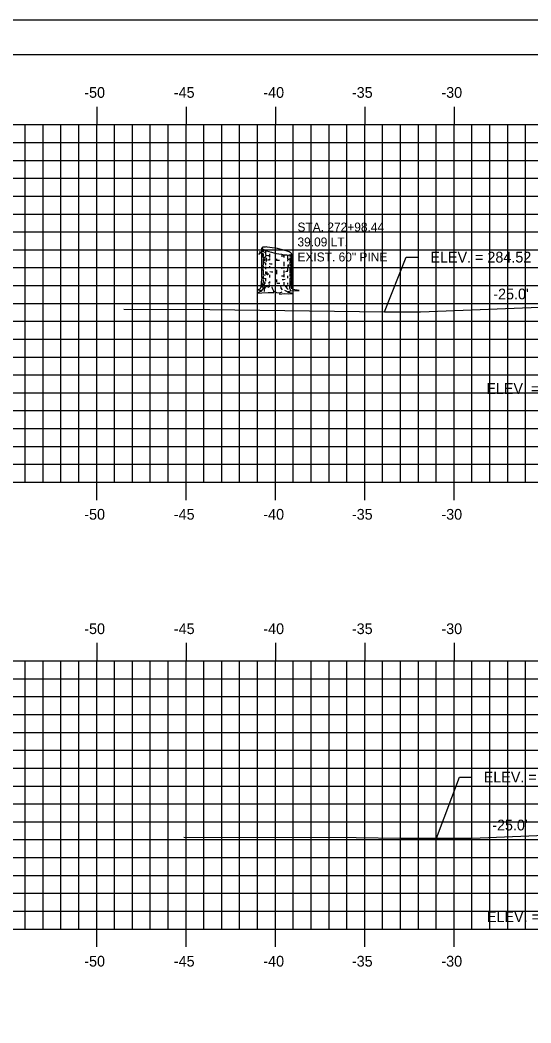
# Model space of a CAD drawing. Extents: x 852672 to 852842, y 366268 to 366378.
# Drawn here: x 852700.8 to 852729.4, y 366322.1 to 366378.2 of the extents above; entities that cross this region are included whole.
import ezdxf

# ---------------------------------------------------------------- set-up
doc = ezdxf.new("R2010")
doc.units = 0
for name, color, linetype in [('BORDER', 7, 'Continuous'), ('D_Text_Monospaced', 7, 'Continuous'), ('D_Text_Standard', 7, 'Continuous'), ('H_V ANNOTATION', 7, 'Continuous'), ('MAJOR', 7, 'Continuous'), ('MINOR', 7, 'Continuous'), ('PLOT BOUNDARY', 7, 'Continuous'), ('S_Roadway_Centerline', 7, 'Continuous'), ('S_Trees_Conifer_Pay', 7, 'Continuous')]:
    doc.layers.add(name, color=color, linetype=linetype)

msp = doc.modelspace()

# ---------------------------------------------------------------- linework, layer by layer
at = {"layer": 'BORDER'}
msp.add_line((852840.097, 366376.236), (852680.097, 366376.236), dxfattribs=at)
at = {"layer": 'D_Text_Standard'}
for points in [[(852721.194, 366361.85), (852722.411, 366364.913), (852723.091, 366364.913)], [(852724.103, 366332.417), (852725.395, 366335.829), (852726.075, 366335.829)]]:
    msp.add_lwpolyline(points, dxfattribs=at)
at = {"layer": 'MAJOR'}
for p, q in [((852705.096, 366373.329), (852705.096, 366372.327)), ((852710.096, 366373.329), (852710.096, 366372.327)), ((852715.096, 366373.329), (852715.096, 366372.327)), ((852720.096, 366373.329), (852720.096, 366372.327)), ((852725.096, 366373.329), (852725.096, 366372.327)), ((852685.096, 366372.327), (852825.096, 366372.327)), ((852685.096, 366372.327), (852825.096, 366372.327)), ((852705.096, 366352.327), (852705.096, 366372.327)), ((852710.096, 366352.327), (852710.096, 366372.327)), ((852715.096, 366352.327), (852715.096, 366372.327)), ((852720.096, 366352.327), (852720.096, 366372.327)), ((852725.096, 366352.327), (852725.096, 366372.327)), ((852685.096, 366367.327), (852825.096, 366367.327)), ((852685.096, 366362.327), (852825.096, 366362.327)), ((852685.096, 366357.327), (852825.096, 366357.327)), ((852685.096, 366352.327), (852825.096, 366352.327)), ((852685.096, 366352.327), (852825.096, 366352.327)), ((852705.096, 366351.325), (852705.096, 366352.327)), ((852710.096, 366351.325), (852710.096, 366352.327)), ((852715.096, 366351.325), (852715.096, 366352.327)), ((852720.096, 366351.325), (852720.096, 366352.327)), ((852725.096, 366351.325), (852725.096, 366352.327)), ((852705.096, 366343.329), (852705.096, 366342.327)), ((852710.096, 366343.329), (852710.096, 366342.327)), ((852715.096, 366343.329), (852715.096, 366342.327)), ((852720.096, 366343.329), (852720.096, 366342.327)), ((852725.096, 366343.329), (852725.096, 366342.327)), ((852685.096, 366342.327), (852825.096, 366342.327)), ((852685.096, 366342.327), (852825.096, 366342.327)), ((852705.096, 366327.327), (852705.096, 366342.327)), ((852710.096, 366327.327), (852710.096, 366342.327)), ((852715.096, 366327.327), (852715.096, 366342.327)), ((852720.096, 366327.327), (852720.096, 366342.327)), ((852725.096, 366327.327), (852725.096, 366342.327)), ((852685.096, 366337.327), (852825.096, 366337.327)), ((852685.096, 366332.327), (852825.096, 366332.327)), ((852685.096, 366327.327), (852825.096, 366327.327)), ((852685.096, 366327.327), (852825.096, 366327.327)), ((852705.096, 366326.325), (852705.096, 366327.327)), ((852710.096, 366326.325), (852710.096, 366327.327)), ((852715.096, 366326.325), (852715.096, 366327.327)), ((852720.096, 366326.325), (852720.096, 366327.327)), ((852725.096, 366326.325), (852725.096, 366327.327))]:
    msp.add_line(p, q, dxfattribs=at)
at = {"layer": 'MINOR'}
for p, q in [((852701.096, 366352.327), (852701.096, 366372.327)), ((852702.096, 366352.327), (852702.096, 366372.327)), ((852703.096, 366352.327), (852703.096, 366372.327)), ((852704.096, 366352.327), (852704.096, 366372.327)), ((852706.096, 366352.327), (852706.096, 366372.327)), ((852707.096, 366352.327), (852707.096, 366372.327)), ((852708.096, 366352.327), (852708.096, 366372.327)), ((852709.096, 366352.327), (852709.096, 366372.327)), ((852711.096, 366352.327), (852711.096, 366372.327)), ((852712.096, 366352.327), (852712.096, 366372.327)), ((852713.096, 366352.327), (852713.096, 366372.327)), ((852714.096, 366352.327), (852714.096, 366372.327)), ((852716.096, 366352.327), (852716.096, 366372.327)), ((852717.096, 366352.327), (852717.096, 366372.327)), ((852718.096, 366352.327), (852718.096, 366372.327)), ((852719.096, 366352.327), (852719.096, 366372.327)), ((852721.096, 366352.327), (852721.096, 366372.327)), ((852722.096, 366352.327), (852722.096, 366372.327)), ((852723.096, 366352.327), (852723.096, 366372.327)), ((852724.096, 366352.327), (852724.096, 366372.327)), ((852726.096, 366352.327), (852726.096, 366372.327)), ((852727.096, 366352.327), (852727.096, 366372.327)), ((852728.096, 366352.327), (852728.096, 366372.327)), ((852729.096, 366352.327), (852729.096, 366372.327)), ((852685.096, 366371.327), (852825.096, 366371.327)), ((852685.096, 366370.327), (852825.096, 366370.327)), ((852685.096, 366369.327), (852825.096, 366369.327)), ((852685.096, 366368.327), (852825.096, 366368.327)), ((852685.096, 366366.327), (852825.096, 366366.327)), ((852685.096, 366365.327), (852825.096, 366365.327)), ((852685.096, 366364.327), (852825.096, 366364.327)), ((852685.096, 366363.327), (852825.096, 366363.327)), ((852685.096, 366361.327), (852825.096, 366361.327)), ((852685.096, 366360.327), (852825.096, 366360.327)), ((852685.096, 366359.327), (852825.096, 366359.327)), ((852685.096, 366358.327), (852825.096, 366358.327)), ((852685.096, 366356.327), (852825.096, 366356.327)), ((852685.096, 366355.327), (852825.096, 366355.327)), ((852685.096, 366354.327), (852825.096, 366354.327)), ((852685.096, 366353.327), (852825.096, 366353.327)), ((852701.096, 366327.327), (852701.096, 366342.327)), ((852702.096, 366327.327), (852702.096, 366342.327)), ((852703.096, 366327.327), (852703.096, 366342.327)), ((852704.096, 366327.327), (852704.096, 366342.327)), ((852706.096, 366327.327), (852706.096, 366342.327)), ((852707.096, 366327.327), (852707.096, 366342.327)), ((852708.096, 366327.327), (852708.096, 366342.327)), ((852709.096, 366327.327), (852709.096, 366342.327)), ((852711.096, 366327.327), (852711.096, 366342.327)), ((852712.096, 366327.327), (852712.096, 366342.327)), ((852713.096, 366327.327), (852713.096, 366342.327)), ((852714.096, 366327.327), (852714.096, 366342.327)), ((852716.096, 366327.327), (852716.096, 366342.327)), ((852717.096, 366327.327), (852717.096, 366342.327)), ((852718.096, 366327.327), (852718.096, 366342.327)), ((852719.096, 366327.327), (852719.096, 366342.327)), ((852721.096, 366327.327), (852721.096, 366342.327)), ((852722.096, 366327.327), (852722.096, 366342.327)), ((852723.096, 366327.327), (852723.096, 366342.327)), ((852724.096, 366327.327), (852724.096, 366342.327)), ((852726.096, 366327.327), (852726.096, 366342.327)), ((852727.096, 366327.327), (852727.096, 366342.327)), ((852728.096, 366327.327), (852728.096, 366342.327)), ((852729.096, 366327.327), (852729.096, 366342.327)), ((852685.096, 366341.327), (852825.096, 366341.327)), ((852685.096, 366340.327), (852825.096, 366340.327)), ((852685.096, 366339.327), (852825.096, 366339.327)), ((852685.096, 366338.327), (852825.096, 366338.327)), ((852685.096, 366336.327), (852825.096, 366336.327)), ((852685.096, 366335.327), (852825.096, 366335.327)), ((852685.096, 366334.327), (852825.096, 366334.327)), ((852685.096, 366333.327), (852825.096, 366333.327)), ((852685.096, 366331.327), (852825.096, 366331.327)), ((852685.096, 366330.327), (852825.096, 366330.327)), ((852685.096, 366329.327), (852825.096, 366329.327)), ((852685.096, 366328.327), (852825.096, 366328.327))]:
    msp.add_line(p, q, dxfattribs=at)
at = {"layer": 'PLOT BOUNDARY'}
msp.add_lwpolyline([(852672.003, 366268.177), (852842.003, 366268.177), (852842.003, 366378.177), (852672.003, 366378.177)], close=True, dxfattribs=at)
at = {"layer": 'S_Roadway_Centerline'}
for points in [[(852706.614, 366362.002), (852711.434, 366361.992), (852721.194, 366361.85), (852723.222, 366361.85), (852731.301, 366362.174), (852731.997, 366362.154), (852734.142, 366361.931), (852735.024, 366362.055), (852736.929, 366362.331), (852740.774, 366362.627), (852743.133, 366362.791), (852747.417, 366362.872), (852755.187, 366363.083), (852759.991, 366362.96), (852768.422, 366362.719), (852776.31, 366362.408), (852781.428, 366362.26), (852782.594, 366362.294), (852784.415, 366362.377), (852787.287, 366362.402), (852792.84, 366362.746), (852804.042, 366363.313), (852809.881, 366363.563), (852812.01, 366363.649)], [(852709.973, 366332.472), (852719.622, 366332.453), (852722.098, 366332.417), (852726.107, 366332.417), (852731.078, 366332.617)]]:
    msp.add_lwpolyline(points, dxfattribs=at)
at = {"layer": 'S_Trees_Conifer_Pay'}
for p, q in [((852714.346, 366363.778), (852714.346, 366365.425)), ((852714.417, 366365.353), (852714.417, 366365.19)), ((852714.535, 366365.292), (852714.535, 366365.069)), ((852714.417, 366365.123), (852714.417, 366364.995)), ((852714.417, 366364.808), (852714.417, 366364.472)), ((852714.478, 366364.797), (852714.529, 366364.737)), ((852714.535, 366364.98), (852714.535, 366364.933)), ((852714.763, 366365.096), (852714.763, 366364.896)), ((852714.763, 366364.839), (852714.763, 366364.75)), ((852715.154, 366364.822), (852715.154, 366364.727)), ((852715.559, 366365.054), (852715.559, 366364.886)), ((852715.559, 366364.649), (852715.559, 366364.412)), ((852715.779, 366365.033), (852715.779, 366364.801)), ((852715.779, 366364.76), (852715.779, 366364.686)), ((852715.904, 366365.041), (852715.904, 366364.944)), ((852715.904, 366364.869), (852715.904, 366364.665)), ((852715.963, 366365.052), (852715.963, 366364.581)), ((852716.01, 366363.368), (852716.01, 366365.09)), ((852714.417, 366364.435), (852714.417, 366364.272)), ((852714.417, 366364.225), (852714.417, 366364.008)), ((852714.535, 366364.598), (852714.535, 366364.466)), ((852714.535, 366364.355), (852714.535, 366364.245)), ((852714.535, 366364.11), (852714.535, 366363.968)), ((852714.763, 366364.402), (852714.763, 366364.297)), ((852715.154, 366364.209), (852715.154, 366364.134)), ((852715.154, 366364.11), (852715.154, 366363.961)), ((852715.559, 366364.167), (852715.559, 366364.015)), ((852715.779, 366364.283), (852715.779, 366364.144)), ((852715.904, 366364.608), (852715.904, 366364.408)), ((852715.904, 366364.361), (852715.904, 366364.025)), ((852715.963, 366364.517), (852715.963, 366364.209)), ((852715.963, 366364.161), (852715.963, 366363.669)), ((852714.417, 366363.978), (852714.417, 366363.903)), ((852714.417, 366363.863), (852714.417, 366363.69)), ((852714.535, 366363.741), (852714.535, 366363.568)), ((852714.763, 366363.93), (852714.763, 366363.784)), ((852714.763, 366363.552), (852714.763, 366363.463)), ((852715.154, 366363.669), (852715.154, 366363.516)), ((852715.559, 366363.972), (852715.559, 366363.798)), ((852715.559, 366363.521), (852715.559, 366363.368)), ((852715.779, 366363.873), (852715.779, 366363.731)), ((852715.904, 366363.972), (852715.904, 366363.836)), ((852715.904, 366363.737), (852715.904, 366363.358)), ((852715.963, 366363.615), (852715.963, 366363.368)), ((852715.342, 366362.911), (852715.468, 366362.975)), ((852715.779, 366362.975), (852715.616, 366363.039)), ((852715.779, 366363.469), (852715.779, 366363.375))]:
    msp.add_line(p, q, dxfattribs=at)
for points in [[(852714.529, 366364.923), (852714.492, 366364.849), (852714.445, 366364.906), (852714.387, 366364.974), (852714.295, 366365.168), (852714.23, 366365.215), (852714.199, 366365.222)], [(852714.3, 366365.156), (852714.224, 366365.164), (852714.152, 366365.065)], [(852714.514, 366364.67), (852714.478, 366364.797), (852714.414, 366364.913), (852714.383, 366364.98), (852714.314, 366365.127)], [(852714.562, 366364.886), (852714.593, 366364.801), (852714.597, 366364.734), (852714.566, 366364.67)], [(852714.692, 366363.997), (852714.679, 366363.92), (852714.632, 366363.93), (852714.644, 366364.097)], [(852715.831, 366364.396), (852715.837, 366364.491), (852715.793, 366364.468), (852715.793, 366364.373)], [(852714.346, 366363.778), (852714.295, 366363.516), (852714.278, 366363.243), (852714.22, 366363.117), (852714.085, 366363.087), (852714.315, 366363.049), (852714.315, 366363.049), (852714.309, 366363.002), (852714.062, 366362.907), (852714.336, 366362.924), (852714.692, 366362.944), (852715.013, 366362.934), (852715.007, 366363.016), (852715.155, 366362.934), (852715.342, 366362.911), (852715.318, 366362.843), (852715.585, 366362.886), (852715.806, 366362.86), (852716.098, 366362.877), (852715.81, 366362.934), (852715.779, 366362.975), (852715.942, 366363.033), (852716.178, 366363.043), (852716.419, 366363.043), (852716.077, 366363.101), (852716.036, 366363.181), (852716.01, 366363.368)], [(852714.42, 366363.636), (852714.414, 366363.49), (852714.367, 366363.422), (852714.356, 366363.222)], [(852714.519, 366363.49), (852714.445, 366363.385), (852714.44, 366363.212), (852714.315, 366363.049)], [(852714.478, 366362.996), (852714.492, 366363.134), (852714.566, 366363.263)], [(852714.756, 366363.385), (852714.745, 366363.259), (852714.671, 366363.216)], [(852715.007, 366363.016), (852714.932, 366363.158), (852714.923, 366363.259)], [(852715.495, 366363.087), (852715.427, 366363.181), (852715.4, 366363.321)], [(852715.721, 366363.327), (852715.721, 366363.195), (852715.81, 366363.096)], [(852715.884, 366363.3), (852715.878, 366363.185), (852715.931, 366363.096), (852715.942, 366363.033)], [(852715.962, 366363.321), (852715.983, 366363.243), (852716.003, 366363.148)]]:
    msp.add_lwpolyline(points, dxfattribs=at)
for centre, radius, start, end in [((852714.368, 366365.425), 0.0226, 156.5926, 168.2806), ((852714.368, 366365.425), 0.0226, 168.2806, 179.9685), ((852714.372, 366365.425), 0.0264, 179.9685, 190.7806), ((852714.377, 366365.426), 0.0314, 190.7806, 203.4842), ((852714.379, 366365.299), 0.0334, 185.7849, 196.0515), ((852714.389, 366365.302), 0.0441, 196.0515, 210), ((852714.372, 366365.424), 0.0264, 145.7806, 156.5926), ((852714.397, 366365.435), 0.0527, 203.4842, 213.2806), ((852714.376, 366365.421), 0.0314, 133.077, 145.7806), ((852714.405, 366365.311), 0.0624, 210, 228.7494), ((852714.421, 366365.451), 0.0817, 213.2806, 227.6113), ((852714.391, 366365.405), 0.0527, 123.2806, 133.077), ((852714.406, 366365.381), 0.0817, 108.9499, 123.2806), ((852714.478, 366365.394), 0.172, 228.7494, 240), ((852714.535, 366365.575), 0.251, 227.6113, 235.7806), ((852714.461, 366365.221), 0.251, 100.7806, 108.9499), ((852714.845, 366366.031), 0.802, 235.7806, 251.9406), ((852714.564, 366364.68), 0.802, 84.6206, 100.7806), ((852714.677, 366365.739), 0.571, 247.5868, 255.5683), ((852716.201, 366370.193), 5.179, 251.9406, 258.2806), ((852714.154, 366360.322), 5.179, 78.2806, 84.6206), ((852714.154, 366360.322), 5.179, 71.9406, 78.2806), ((852715.511, 366364.484), 0.802, 55.7806, 71.9406), ((852714.379, 366365.144), 0.0334, 185.7849, 196.0515), ((852714.379, 366364.7), 0.0334, 185.7849, 196.0515), ((852714.389, 366365.147), 0.0441, 196.0515, 210), ((852714.405, 366365.157), 0.0624, 210, 228.7494), ((852714.478, 366365.239), 0.172, 228.7494, 240), ((852714.677, 366365.584), 0.571, 240, 242.9763), ((852714.677, 366365.14), 0.571, 242.9571, 255.5507), ((852714.677, 366365.584), 0.571, 255.6333, 261.8968), ((852715.178, 366369.102), 4.124, 261.8968, 263.762), ((852715.179, 366368.869), 4.124, 262.9442, 264.2151), ((852716.201, 366370.193), 5.179, 258.2806, 264.6206), ((852715.179, 366368.869), 4.124, 269.6419, 270), ((852715.179, 366368.869), 4.124, 270, 271.9249), ((852715.178, 366369.102), 4.124, 273.2669, 275.3045), ((852715.791, 366365.835), 0.802, 264.6206, 280.7806), ((852715.68, 366365.351), 0.571, 282.0154, 293.1403), ((852715.679, 366365.14), 0.571, 292.9413, 300), ((852715.894, 366365.293), 0.251, 280.7806, 288.9499), ((852715.821, 366364.939), 0.251, 47.6113, 55.7806), ((852715.68, 366365.351), 0.571, 299.6633, 300), ((852715.879, 366365.006), 0.172, 300, 311.2506), ((852715.949, 366365.134), 0.0817, 288.9499, 303.2806), ((852715.935, 366365.064), 0.0817, 33.2806, 47.6113), ((852715.952, 366364.924), 0.0624, 311.2506, 330), ((852715.965, 366365.109), 0.0527, 303.2806, 313.077), ((852715.98, 366365.094), 0.0314, 313.077, 325.7806), ((852715.959, 366365.08), 0.0527, 23.4842, 33.2806), ((852715.984, 366365.091), 0.0264, 325.7806, 336.5926), ((852715.967, 366364.915), 0.0441, 330, 343.9485), ((852715.978, 366365.089), 0.0314, 10.7806, 23.4842), ((852715.987, 366365.09), 0.0226, 336.5926, 348.2806), ((852715.983, 366365.09), 0.0264, 359.9685, 10.7806), ((852715.987, 366365.09), 0.0226, 348.2806, 359.9685), ((852715.978, 366364.912), 0.0334, 0, 16.0515), ((852715.978, 366364.912), 0.0334, 343.9485, 360), ((852714.38, 366364.465), 0.0334, 185.7849, 196.0515), ((852714.38, 366364.255), 0.0334, 185.7849, 196.0515), ((852714.391, 366364.468), 0.0441, 196.0515, 210), ((852714.391, 366364.258), 0.0441, 196.0515, 210), ((852714.407, 366364.477), 0.0624, 210, 228.7494), ((852714.407, 366364.267), 0.0624, 210, 228.7494), ((852714.479, 366364.559), 0.172, 228.7494, 240), ((852714.479, 366364.349), 0.172, 228.7494, 240), ((852714.678, 366364.905), 0.571, 240, 242.8104), ((852714.678, 366364.695), 0.571, 240, 242.8104), ((852714.678, 366364.905), 0.571, 253.0704, 261.8968), ((852715.179, 366368.422), 4.124, 261.8968, 262.3875), ((852715.178, 366368.658), 4.124, 264.0496, 266.2948), ((852715.179, 366368.212), 4.124, 264.5431, 266.8507), ((852715.179, 366368.212), 4.124, 269.6419, 270), ((852715.179, 366368.422), 4.124, 273.3324, 275.919), ((852715.179, 366368.212), 4.124, 276.8526, 278.1032), ((852715.68, 366364.695), 0.571, 278.1032, 280.7293), ((852715.68, 366364.695), 0.571, 293.1403, 300), ((852715.68, 366364.905), 0.571, 299.6633, 300), ((852715.879, 366364.559), 0.172, 300, 311.2506), ((852715.879, 366364.349), 0.172, 300, 311.2506), ((852715.952, 366364.477), 0.0624, 311.2506, 330), ((852715.952, 366364.267), 0.0624, 311.2506, 330), ((852715.967, 366364.468), 0.0441, 330, 343.9485), ((852715.967, 366364.258), 0.0441, 330, 343.9485), ((852715.978, 366364.465), 0.0334, 0, 16.0515), ((852715.978, 366364.465), 0.0334, 343.9485, 360), ((852715.978, 366364.255), 0.0334, 0, 16.0515), ((852715.978, 366364.255), 0.0334, 343.9485, 360), ((852714.38, 366363.82), 0.0334, 185.7849, 196.0515), ((852714.391, 366363.823), 0.0441, 196.0515, 210), ((852714.407, 366363.832), 0.0624, 210, 228.7494), ((852714.479, 366363.915), 0.172, 228.7494, 240), ((852714.678, 366364.26), 0.571, 240, 250.7093), ((852714.678, 366364.458), 0.571, 242.8104, 254.6017), ((852714.678, 366364.064), 0.571, 242.7279, 251.4933), ((852715.179, 366367.975), 4.124, 273.6807, 275.284), ((852715.179, 366367.778), 4.124, 274.1603, 276.5009), ((852715.68, 366364.458), 0.571, 293.1403, 300), ((852715.691, 366364.266), 0.571, 291.9732, 298.7631), ((852715.68, 366364.064), 0.571, 293.1403, 300), ((852715.879, 366364.113), 0.172, 300, 311.2506), ((852715.879, 366363.719), 0.172, 300, 311.2506), ((852715.952, 366364.03), 0.0624, 311.2506, 330), ((852715.952, 366363.637), 0.0624, 311.2506, 330), ((852715.967, 366364.021), 0.0441, 330, 343.9485), ((852715.967, 366363.628), 0.0441, 330, 343.9485), ((852715.978, 366364.018), 0.0334, 0, 16.0515), ((852715.978, 366364.018), 0.0334, 343.9485, 360), ((852715.978, 366363.82), 0.0334, 0, 16.0515), ((852715.978, 366363.625), 0.0334, 0, 16.0515), ((852715.978, 366363.625), 0.0334, 343.9485, 360), ((852714.38, 366363.404), 0.0334, 185.7849, 196.0515), ((852714.391, 366363.407), 0.0441, 196.0515, 210), ((852714.407, 366363.417), 0.0624, 210, 228.7494), ((852714.479, 366363.499), 0.172, 228.7494, 240), ((852714.678, 366363.844), 0.571, 258.363, 261.8968), ((852715.179, 366367.362), 4.124, 261.8968, 262.6316), ((852715.179, 366367.582), 4.124, 263.2104, 264.2151), ((852715.179, 366367.582), 4.124, 269.8672, 270), ((852715.179, 366367.582), 4.124, 270, 272.1883), ((852715.179, 366367.362), 4.124, 276.488, 277.5562), ((852715.68, 366363.844), 0.571, 295.4686, 300), ((852715.879, 366363.499), 0.172, 300, 311.2506), ((852715.952, 366363.417), 0.0624, 311.2506, 330), ((852715.967, 366363.407), 0.0441, 330, 343.9485), ((852715.978, 366363.404), 0.0334, 0, 16.0515), ((852715.978, 366363.404), 0.0334, 343.9485, 360)]:
    msp.add_arc(centre, radius, start, end, dxfattribs=at)

# ---------------------------------------------------------------- texts
at = {"layer": 'D_Text_Monospaced'}
for s, height, p in [('STA. 272+98.44', 0.49998, (852716.33, 366366.347)), ('39.09 LT.', 0.5, (852716.33, 366365.513)), ('EXIST. 60" PINE', 0.49998, (852716.33, 366364.673))]:
    msp.add_text(s, height=height, dxfattribs=at).set_placement(p)
at = {"layer": 'D_Text_Standard'}
for s, p in [('ELEV. = 284.52', (852723.771, 366364.613)), ("-25.0'", (852727.289, 366362.553)), ('ELEV. = 280.24', (852726.899, 366357.267)), ('ELEV. = 285.09', (852726.755, 366335.529)), ("-25.0'", (852727.228, 366332.844)), ('ELEV. = 280.69', (852726.931, 366327.717))]:
    msp.add_text(s, height=0.6, dxfattribs=at).set_placement(p)
at = {"layer": 'H_V ANNOTATION'}
for s, p in [('-50', (852704.401, 366373.827)), ('-45', (852709.414, 366373.827)), ('-40', (852714.422, 366373.827)), ('-35', (852719.377, 366373.827)), ('-30', (852724.385, 366373.827)), ('-50', (852704.401, 366350.227)), ('-45', (852709.414, 366350.227)), ('-40', (852714.422, 366350.227)), ('-35', (852719.377, 366350.227)), ('-30', (852724.385, 366350.227)), ('-50', (852704.401, 366343.827)), ('-45', (852709.414, 366343.827)), ('-40', (852714.422, 366343.827)), ('-35', (852719.377, 366343.827)), ('-30', (852724.385, 366343.827)), ('-50', (852704.401, 366325.227)), ('-45', (852709.414, 366325.227)), ('-40', (852714.422, 366325.227)), ('-35', (852719.377, 366325.227)), ('-30', (852724.385, 366325.227))]:
    msp.add_text(s, height=0.6, dxfattribs=at).set_placement(p)

doc.saveas('drawing.dxf')
